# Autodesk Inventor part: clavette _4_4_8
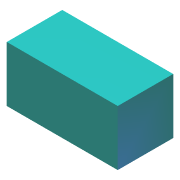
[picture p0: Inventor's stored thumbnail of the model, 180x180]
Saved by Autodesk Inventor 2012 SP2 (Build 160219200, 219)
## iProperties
Created: 2013-04
Part Number: clavette _4_4_8
Material: Default
Document SubType Name: Modeling
Designer: papa
Density: 1 g/cm^3
Mass: 0.128 g
Surface Area: 1.6 cm^2
Volume: 0.128 cm^3
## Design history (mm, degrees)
node "clavette _4_4_81"
node "clavette _4_4_8"
node "Base1"
